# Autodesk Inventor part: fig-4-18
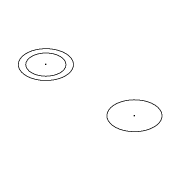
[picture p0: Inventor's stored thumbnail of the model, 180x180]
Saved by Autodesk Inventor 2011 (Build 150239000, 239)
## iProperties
Created: 2005-02
Part Number: fig-4-18
Document SubType Name: Modeling
Designer: CADCIM
Manufacturer: Standard
Standards Organization: Custom
Density: 1 g/cm^3
Author: CADCIM
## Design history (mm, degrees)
sketch "Sketch1"
  geometry: C1 r 7.935 at (-23.563, 7.599); C2 r 7.935 at (12.452, 7.599); C3 r 5.782 at (-23.563, 7.599)
  constraints: 3 centre point, 1 coincident, 1 equal radius, 1 other
